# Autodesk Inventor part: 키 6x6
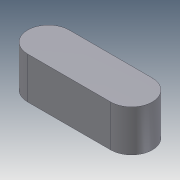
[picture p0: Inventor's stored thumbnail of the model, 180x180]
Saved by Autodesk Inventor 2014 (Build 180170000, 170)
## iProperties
Company: 한국ATC센터
Created: 2013-01
Part Number: 키 6x6
Document SubType Name: Modeling
Designer: KYOUNG IL JANG
Density: 7.25 g/cm^3
Material: 주철
Mass: 4.36193 g
Surface Area: 4.57646 cm^2
Volume: 0.601646 cm^3
Appearance: 강철
Author: KYOUNG IL JANG
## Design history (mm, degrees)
sketch "스케치1"
  geometry: L1 (-6, -3)-(6, -3); L2 (6, 3)-(-6, 3); A1 r 3 centre (6, 0) between (6, -3) and (6, 3); A2 r 3 centre (-6, 0) between (-6, 3) and (-6, -3); 2 further points
  constraints: 4 end point, 4 point on circle, 4 tangent, 2 centre point, 1 horizontal, 1 horizontal alignment, 1 midpoint, 1 parallel, 1 vertical alignment
  dimensions: "d0" = 18 dimension on A1 A2; "d1" = 6 distance between parallel lines of L1 L2
extrude "돌출1" new body sketch "스케치1" stored distance "d2" = 6; taper "d3" = 0 deg
node "솔리드1"
